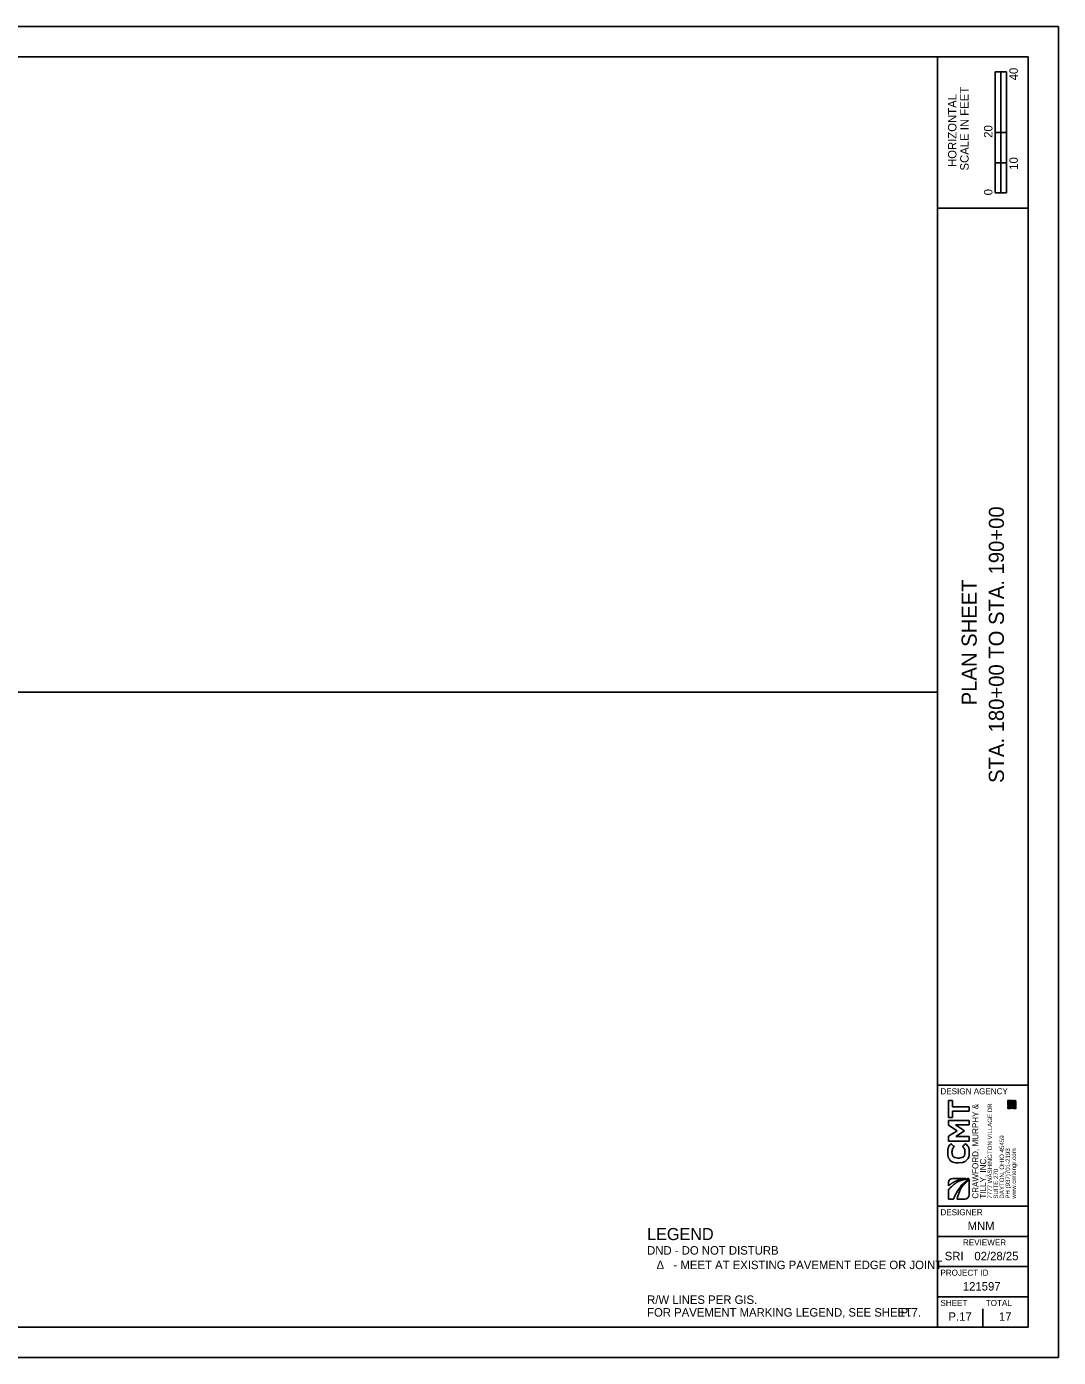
# Model space of a CAD drawing. Extents: x -0.1 to 34, y 0 to 22.
# Drawn here: x 16.94 to 34, y 0 to 22 of the extents above; entities that cross this region are included whole.
import ezdxf

# ---------------------------------------------------------------- set-up
doc = ezdxf.new("R2010")
doc.units = 0
for name, color, linetype in [('Common-Title block info', 7, 'Continuous'), ('Default', 7, 'Continuous'), ('LOGOS', 7, 'Continuous'), ('SH_Border', 7, 'Continuous'), ('SH_Cut_Line', 7, 'Continuous'), ('SH_Data', 7, 'Continuous'), ('SH_Text', 7, 'Continuous')]:
    doc.layers.add(name, color=color, linetype=linetype)

msp = doc.modelspace()

# ---------------------------------------------------------------- linework, layer by layer
at = {"layer": 'Common-Title block info'}
for p, q in [((32.184, 2.889), (32.184, 2.838)), ((32.47, 2.96), (32.254, 2.96)), ((32.525, 2.96), (32.525, 2.96)), ((32.526, 2.688), (32.526, 2.941)), ((32.184, 2.773), (32.184, 2.618)), ((32.184, 2.618), (32.267, 2.618)), ((32.324, 2.618), (32.455, 2.618))]:
    msp.add_line(p, q, dxfattribs=at)
msp.add_lwpolyline([(32.526, 2.941), (32.526, 2.941)], dxfattribs=at)
for centre, start, end in [((32.254, 2.889), 90, 180), ((32.455, 2.688), 270, 360)]:
    msp.add_arc(centre, 0.0708, start, end, dxfattribs=at)
for points, degree in [([(32.525, 2.96), (32.393, 2.934), (32.272, 2.867), (32.184, 2.773)], 2), ([(32.184, 2.838), (32.266, 2.9), (32.365, 2.94), (32.47, 2.96)], 2), ([(32.267, 2.618), (32.267, 2.618), (32.267, 2.618), (32.267, 2.618), (32.323, 2.751), (32.412, 2.869), (32.525, 2.96)], 3), ([(32.526, 2.941), (32.434, 2.857), (32.367, 2.761), (32.324, 2.618)], 2)]:
    msp.add_open_spline(points, degree=degree, dxfattribs=at)
at = {"layer": 'LOGOS'}
for p, q in [((32.182, 3.964), (32.182, 4.248)), ((32.182, 4.248), (32.252, 4.248)), ((32.252, 4.248), (32.252, 4.143)), ((32.252, 3.964), (32.182, 3.964)), ((32.252, 4.143), (32.525, 4.143)), ((32.252, 4.068), (32.252, 3.964)), ((32.525, 4.068), (32.252, 4.068)), ((32.525, 4.143), (32.525, 4.068)), ((32.182, 3.837), (32.182, 3.918)), ((32.182, 3.918), (32.525, 3.918)), ((32.327, 3.747), (32.182, 3.837)), ((32.182, 3.657), (32.327, 3.747)), ((32.525, 3.843), (32.301, 3.843)), ((32.301, 3.843), (32.448, 3.747)), ((32.448, 3.745), (32.303, 3.649)), ((32.448, 3.747), (32.448, 3.745)), ((32.525, 3.918), (32.525, 3.843)), ((32.182, 3.575), (32.182, 3.657)), ((32.525, 3.575), (32.182, 3.575)), ((32.303, 3.649), (32.525, 3.649)), ((32.525, 3.649), (32.525, 3.575))]:
    msp.add_line(p, q, dxfattribs=at)
for points in [[(33.284, 4.243), (33.279, 4.243), (33.279, 4.239), (33.275, 4.239), (33.275, 4.23), (33.265, 4.23), (33.265, 4.234), (33.261, 4.234), (33.261, 4.239), (33.252, 4.239), (33.252, 4.225), (33.256, 4.225), (33.256, 4.221), (33.247, 4.221), (33.247, 4.216), (33.252, 4.216), (33.252, 4.212), (33.238, 4.212), (33.238, 4.221), (33.234, 4.221), (33.234, 4.225), (33.238, 4.225), (33.238, 4.221), (33.247, 4.221), (33.247, 4.225), (33.243, 4.225), (33.243, 4.234), (33.229, 4.234), (33.229, 4.239), (33.225, 4.239), (33.225, 4.243), (33.229, 4.243), (33.229, 4.239), (33.234, 4.239), (33.234, 4.243), (33.238, 4.243), (33.238, 4.248), (33.216, 4.248), (33.216, 4.243), (33.22, 4.243), (33.22, 4.23), (33.229, 4.23), (33.229, 4.225), (33.216, 4.225), (33.216, 4.221), (33.225, 4.221), (33.225, 4.216), (33.234, 4.216), (33.234, 4.212), (33.229, 4.212), (33.229, 4.207), (33.225, 4.207), (33.225, 4.216), (33.22, 4.216), (33.22, 4.212), (33.216, 4.212), (33.216, 4.207), (33.22, 4.207), (33.22, 4.203), (33.211, 4.203), (33.211, 4.212), (33.207, 4.212), (33.207, 4.207), (33.198, 4.207), (33.198, 4.203), (33.193, 4.203), (33.193, 4.207), (33.198, 4.207), (33.198, 4.212), (33.189, 4.212), (33.189, 4.207), (33.184, 4.207), (33.184, 4.212), (33.175, 4.212), (33.175, 4.203), (33.17, 4.203), (33.17, 4.207), (33.166, 4.207), (33.166, 4.198), (33.179, 4.198), (33.179, 4.184), (33.184, 4.184), (33.184, 4.189), (33.189, 4.189), (33.189, 4.193), (33.184, 4.193), (33.184, 4.203), (33.189, 4.203), (33.189, 4.193), (33.193, 4.193), (33.193, 4.198), (33.198, 4.198), (33.198, 4.193), (33.193, 4.193), (33.193, 4.189), (33.202, 4.189), (33.202, 4.203), (33.207, 4.203), (33.207, 4.198), (33.211, 4.198), (33.211, 4.193), (33.216, 4.193), (33.216, 4.198), (33.234, 4.198), (33.234, 4.193), (33.238, 4.193), (33.238, 4.184), (33.234, 4.184), (33.234, 4.18), (33.252, 4.18), (33.252, 4.184), (33.261, 4.184), (33.261, 4.18), (33.252, 4.18), (33.252, 4.171), (33.256, 4.171), (33.256, 4.162), (33.261, 4.162), (33.261, 4.166), (33.265, 4.166), (33.265, 4.175), (33.27, 4.175), (33.27, 4.157), (33.279, 4.157), (33.279, 4.166), (33.275, 4.166), (33.275, 4.171), (33.279, 4.171), (33.279, 4.166), (33.284, 4.166), (33.284, 4.157), (33.279, 4.157), (33.279, 4.153), (33.288, 4.153), (33.288, 4.162), (33.297, 4.162), (33.297, 4.171), (33.293, 4.171), (33.293, 4.166), (33.288, 4.166), (33.288, 4.175), (33.279, 4.175), (33.279, 4.18), (33.284, 4.18), (33.284, 4.184), (33.297, 4.184), (33.297, 4.189), (33.293, 4.189), (33.293, 4.193), (33.297, 4.193), (33.297, 4.212), (33.284, 4.212), (33.284, 4.207), (33.293, 4.207), (33.293, 4.203), (33.284, 4.203), (33.284, 4.198), (33.279, 4.198), (33.279, 4.193), (33.275, 4.193), (33.275, 4.198), (33.27, 4.198), (33.27, 4.207), (33.279, 4.207), (33.279, 4.225), (33.284, 4.225)], [(33.198, 4.248), (33.166, 4.248), (33.166, 4.216), (33.198, 4.216)], [(33.179, 4.184), (33.175, 4.184), (33.175, 4.193), (33.166, 4.193), (33.166, 4.171), (33.17, 4.171), (33.17, 4.166), (33.175, 4.166), (33.175, 4.162), (33.17, 4.162), (33.17, 4.157), (33.179, 4.157), (33.179, 4.162), (33.184, 4.162), (33.184, 4.18), (33.179, 4.18)], [(33.193, 4.243), (33.193, 4.221), (33.17, 4.221), (33.17, 4.243)], [(33.189, 4.239), (33.175, 4.239), (33.175, 4.225), (33.189, 4.225)], [(33.202, 4.189), (33.202, 4.184), (33.193, 4.184), (33.193, 4.18), (33.198, 4.18), (33.198, 4.175), (33.202, 4.175), (33.202, 4.171), (33.198, 4.171), (33.198, 4.166), (33.207, 4.166), (33.207, 4.175), (33.211, 4.175), (33.211, 4.18), (33.207, 4.18), (33.207, 4.189)], [(33.216, 4.243), (33.211, 4.243), (33.211, 4.239), (33.207, 4.239), (33.207, 4.23), (33.202, 4.23), (33.202, 4.225), (33.207, 4.225), (33.207, 4.221), (33.202, 4.221), (33.202, 4.212), (33.207, 4.212), (33.207, 4.216), (33.216, 4.216), (33.216, 4.221), (33.211, 4.221), (33.211, 4.225), (33.216, 4.225)], [(33.211, 4.243), (33.211, 4.248), (33.207, 4.248), (33.207, 4.243)], [(33.211, 4.18), (33.216, 4.18), (33.216, 4.175), (33.22, 4.175), (33.22, 4.157), (33.229, 4.157), (33.229, 4.153), (33.234, 4.153), (33.234, 4.162), (33.225, 4.162), (33.225, 4.166), (33.234, 4.166), (33.234, 4.171), (33.229, 4.171), (33.229, 4.175), (33.225, 4.175), (33.225, 4.18), (33.22, 4.18), (33.22, 4.189), (33.211, 4.189)], [(33.225, 4.189), (33.225, 4.193), (33.22, 4.193), (33.22, 4.189)], [(33.234, 4.184), (33.234, 4.189), (33.225, 4.189), (33.225, 4.18), (33.229, 4.18), (33.229, 4.184)], [(33.265, 4.198), (33.265, 4.193), (33.27, 4.193), (33.27, 4.189), (33.279, 4.189), (33.279, 4.184), (33.275, 4.184), (33.275, 4.18), (33.27, 4.18), (33.27, 4.184), (33.265, 4.184), (33.265, 4.189), (33.261, 4.189), (33.261, 4.193), (33.256, 4.193), (33.256, 4.198), (33.252, 4.198), (33.252, 4.193), (33.247, 4.193), (33.247, 4.189), (33.243, 4.189), (33.243, 4.198), (33.238, 4.198), (33.238, 4.207), (33.252, 4.207), (33.252, 4.203), (33.261, 4.203), (33.261, 4.198)], [(33.252, 4.198), (33.252, 4.203), (33.247, 4.203), (33.247, 4.198)], [(33.265, 4.234), (33.27, 4.234), (33.27, 4.243), (33.265, 4.243), (33.265, 4.248), (33.261, 4.248), (33.261, 4.239), (33.265, 4.239)], [(33.275, 4.225), (33.275, 4.212), (33.261, 4.212), (33.261, 4.225)], [(33.27, 4.221), (33.265, 4.221), (33.265, 4.216), (33.27, 4.216)], [(33.279, 4.243), (33.279, 4.248), (33.275, 4.248), (33.275, 4.243)], [(33.279, 4.203), (33.275, 4.203), (33.275, 4.198), (33.279, 4.198)], [(33.284, 4.207), (33.279, 4.207), (33.279, 4.203), (33.284, 4.203)], [(33.288, 4.243), (33.288, 4.248), (33.284, 4.248), (33.284, 4.243)], [(33.284, 4.225), (33.284, 4.221), (33.288, 4.221), (33.288, 4.225)], [(33.297, 4.239), (33.297, 4.243), (33.288, 4.243), (33.288, 4.239)], [(33.293, 4.225), (33.293, 4.234), (33.288, 4.234), (33.288, 4.225)], [(33.288, 4.221), (33.288, 4.216), (33.297, 4.216), (33.297, 4.225), (33.293, 4.225), (33.293, 4.221)], [(33.198, 4.148), (33.166, 4.148), (33.166, 4.117), (33.198, 4.117)], [(33.175, 4.18), (33.175, 4.175), (33.17, 4.175), (33.17, 4.18)], [(33.193, 4.144), (33.193, 4.121), (33.17, 4.121), (33.17, 4.144)], [(33.189, 4.126), (33.189, 4.139), (33.175, 4.139), (33.175, 4.126)], [(33.189, 4.153), (33.189, 4.157), (33.184, 4.157), (33.184, 4.153)], [(33.193, 4.18), (33.189, 4.18), (33.189, 4.175), (33.193, 4.175)], [(33.193, 4.175), (33.193, 4.171), (33.198, 4.171), (33.198, 4.175)], [(33.207, 4.166), (33.207, 4.162), (33.202, 4.162), (33.202, 4.157), (33.193, 4.157), (33.193, 4.153), (33.202, 4.153), (33.202, 4.144), (33.207, 4.144), (33.207, 4.157), (33.211, 4.157), (33.211, 4.162), (33.216, 4.162), (33.216, 4.166)], [(33.198, 4.166), (33.193, 4.166), (33.193, 4.162), (33.198, 4.162)], [(33.211, 4.135), (33.202, 4.135), (33.202, 4.126), (33.211, 4.126)], [(33.229, 4.153), (33.22, 4.153), (33.22, 4.139), (33.216, 4.139), (33.216, 4.148), (33.211, 4.148), (33.211, 4.135), (33.22, 4.135), (33.22, 4.126), (33.225, 4.126), (33.225, 4.13), (33.238, 4.13), (33.238, 4.135), (33.243, 4.135), (33.243, 4.13), (33.252, 4.13), (33.252, 4.126), (33.256, 4.126), (33.256, 4.121), (33.261, 4.121), (33.261, 4.13), (33.256, 4.13), (33.256, 4.139), (33.252, 4.139), (33.252, 4.148), (33.256, 4.148), (33.256, 4.144), (33.261, 4.144), (33.261, 4.153), (33.27, 4.153), (33.27, 4.157), (33.256, 4.157), (33.256, 4.153), (33.252, 4.153), (33.252, 4.157), (33.247, 4.157), (33.247, 4.153), (33.243, 4.153), (33.243, 4.157), (33.238, 4.157), (33.238, 4.153), (33.234, 4.153), (33.234, 4.148), (33.238, 4.148), (33.238, 4.144), (33.243, 4.144), (33.243, 4.148), (33.247, 4.148), (33.247, 4.139), (33.234, 4.139), (33.234, 4.135), (33.225, 4.135), (33.225, 4.139), (33.234, 4.139), (33.234, 4.148), (33.229, 4.148), (33.229, 4.144), (33.225, 4.144), (33.225, 4.148), (33.229, 4.148)], [(33.211, 4.126), (33.211, 4.117), (33.216, 4.117), (33.216, 4.126)], [(33.234, 4.18), (33.229, 4.18), (33.229, 4.175), (33.234, 4.175)], [(33.234, 4.121), (33.234, 4.126), (33.229, 4.126), (33.229, 4.121)], [(33.234, 4.171), (33.243, 4.171), (33.243, 4.166), (33.252, 4.166), (33.252, 4.171), (33.247, 4.171), (33.247, 4.175), (33.234, 4.175)], [(33.238, 4.121), (33.234, 4.121), (33.234, 4.117), (33.238, 4.117)], [(33.243, 4.166), (33.238, 4.166), (33.238, 4.162), (33.243, 4.162)], [(33.238, 4.13), (33.238, 4.121), (33.243, 4.121), (33.243, 4.13)], [(33.252, 4.117), (33.252, 4.121), (33.247, 4.121), (33.247, 4.117)], [(33.297, 4.148), (33.265, 4.148), (33.265, 4.117), (33.297, 4.117)], [(33.293, 4.144), (33.293, 4.121), (33.27, 4.121), (33.27, 4.144)], [(33.288, 4.139), (33.275, 4.139), (33.275, 4.126), (33.288, 4.126)], [(33.288, 4.175), (33.297, 4.175), (33.297, 4.18), (33.288, 4.18)]]:
    msp.add_lwpolyline(points, close=True, dxfattribs=at)
msp.add_open_spline([(32.35, 3.217), (32.35, 3.217), (32.349, 3.217), (32.349, 3.217), (32.251, 3.217), (32.172, 3.29), (32.172, 3.396), (32.172, 3.46), (32.193, 3.499), (32.224, 3.531), (32.224, 3.531), (32.28, 3.483), (32.28, 3.483), (32.256, 3.456), (32.241, 3.43), (32.241, 3.395), (32.241, 3.337), (32.289, 3.296), (32.348, 3.296), (32.348, 3.296), (32.349, 3.296), (32.349, 3.296), (32.407, 3.296), (32.456, 3.337), (32.456, 3.395), (32.456, 3.434), (32.441, 3.458), (32.416, 3.485), (32.416, 3.485), (32.465, 3.533), (32.465, 3.533), (32.502, 3.498), (32.526, 3.459), (32.526, 3.393), (32.526, 3.292), (32.448, 3.217), (32.35, 3.217)], degree=3, dxfattribs=at)
at = {"layer": 'SH_Border'}
for p, q in [((32, 0.5), (32, 21.5)), ((32, 19), (33.5, 19)), ((1.5, 11), (32, 11)), ((32, 4.5), (33.5, 4.5)), ((32, 2.5), (33.5, 2.5)), ((32, 2), (33.5, 2)), ((32, 1.5), (33.5, 1.5)), ((32, 1), (33.5, 1))]:
    msp.add_line(p, q, dxfattribs=at)
msp.add_lwpolyline([(1.5, 21.5), (33.5, 21.5), (33.5, 0.5), (1.5, 0.5)], close=True, dxfattribs=at)
at = {"layer": 'SH_Cut_Line'}
msp.add_lwpolyline([(0, 0), (34, 0), (34, 22), (0, 22)], close=True, dxfattribs=at)
at = {"layer": 'SH_Data'}
for p, q in [((32.957, 19.25), (32.957, 21.25)), ((33.144, 21.25), (32.957, 21.25)), ((32.957, 20.25), (32.957, 21.25)), ((32.957, 21.25), (33.05, 21.25)), ((33.05, 21.25), (33.051, 21.25)), ((33.051, 21.25), (33.051, 20.25)), ((33.144, 21.25), (33.144, 19.25)), ((33.051, 20.25), (32.957, 20.25)), ((33.143, 20.25), (33.05, 20.25)), ((33.05, 20.25), (33.05, 19.75)), ((33.143, 19.75), (33.143, 20.25)), ((33.05, 19.75), (32.957, 19.75)), ((32.957, 19.75), (32.957, 19.25)), ((33.05, 19.25), (33.05, 19.75)), ((33.05, 19.75), (33.143, 19.75)), ((33.144, 19.25), (32.957, 19.25)), ((32.957, 19.25), (33.05, 19.25)), ((32.75, 3.5), (32.75, 3.5)), ((32.375, 0.675), (32.375, 0.675)), ((32.75, 0.5), (32.75, 0.8))]:
    msp.add_line(p, q, dxfattribs=at)

# ---------------------------------------------------------------- texts
at = {"layer": 'Default'}
for s, p in [('R/W LINES PER GIS.', (27.201, 0.884)), ('FOR PAVEMENT MARKING LEGEND, SEE SHEET ', (27.201, 0.674)), ('P.7', (31.394, 0.674)), ('.', (31.676, 0.674))]:
    msp.add_text(s, height=0.14, dxfattribs=at).set_placement(p)
at = {"layer": 'LOGOS'}
for s, height, p in [('CRAWFORD, MURPHY &', 0.1, (32.677, 2.624)), ('7777 WASHINGTON VILLAGE DR', 0.07331, (32.904, 2.624)), ('DAYTON, OHIO 45459', 0.07331, (33.102, 2.624)), ('TILLY, INC.', 0.1, (32.806, 2.624)), ('PH (937)701-2193', 0.07331, (33.2, 2.624)), ('www.cmtengr.com', 0.07331, (33.299, 2.624)), ('SUITE 270', 0.0733, (33.003, 2.624))]:
    msp.add_text(s, height=height, rotation=90, dxfattribs=at).set_placement(p)
at = {"layer": 'SH_Data'}
for s, height, p in [('40', 0.14, (33.33, 21.112)), ('SCALE IN FEET', 0.14, (32.517, 19.621)), ('HORIZONTAL', 0.14, (32.315, 19.679)), ('20', 0.14, (32.91, 20.162)), ('10', 0.14, (33.33, 19.633)), ('0', 0.14, (32.91, 19.211)), ('STA. 180+00 TO STA. 190+00', 0.25, (33.1, 9.497)), ('PLAN SHEET', 0.25, (32.65, 10.78))]:
    msp.add_text(s, height=height, rotation=90, dxfattribs=at).set_placement(p)
for s, height, p in [('DESIGN AGENCY', 0.1, (32.05, 4.35)), ('DESIGNER', 0.1, (32.05, 2.35)), ('MNM', 0.14, (32.499, 2.105)), ('REVIEWER', 0.1, (32.422, 1.85)), ('SRI', 0.14, (32.121, 1.605)), ('02/28/25', 0.14, (32.611, 1.605)), ('PROJECT ID', 0.1, (32.05, 1.35)), ('121597', 0.14, (32.42, 1.105)), ('SHEET', 0.1, (32.05, 0.85)), ('TOTAL', 0.1, (32.8, 0.85)), ('P.17', 0.14, (32.183, 0.605)), ('17', 0.14, (33.018, 0.605))]:
    msp.add_text(s, height=height, dxfattribs=at).set_placement(p)
at = {"layer": 'SH_Text'}
for s, height, p in [('LEGEND', 0.2, (27.201, 1.939)), ('DND - DO NOT DISTURB', 0.14, (27.201, 1.699)), ('   Δ   - MEET AT EXISTING PAVEMENT EDGE OR JOINT', 0.14, (27.201, 1.459))]:
    msp.add_text(s, height=height, dxfattribs=at).set_placement(p)

doc.saveas('drawing.dxf')
